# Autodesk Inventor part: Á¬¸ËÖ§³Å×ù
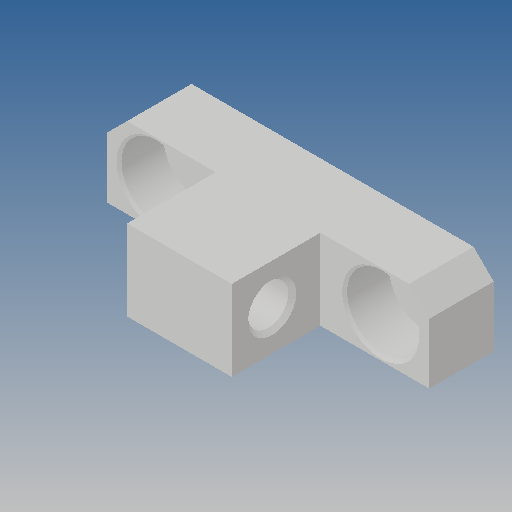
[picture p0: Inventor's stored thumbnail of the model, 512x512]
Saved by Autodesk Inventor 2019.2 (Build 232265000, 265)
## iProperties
Created: 2013-07
Part Number: Á¬¸ËÖ§³Å×ù
Material: Ogólny
Document SubType Name: Modeling
Designer: CADENGINEERING4
Density: 1 g/cm^3
Appearance: Domyślna
Author: CADENGINEERING4
Revision Number: ÈÎºÎ
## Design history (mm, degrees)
feature "µ¹½Ç4"
node "Bryła1"
